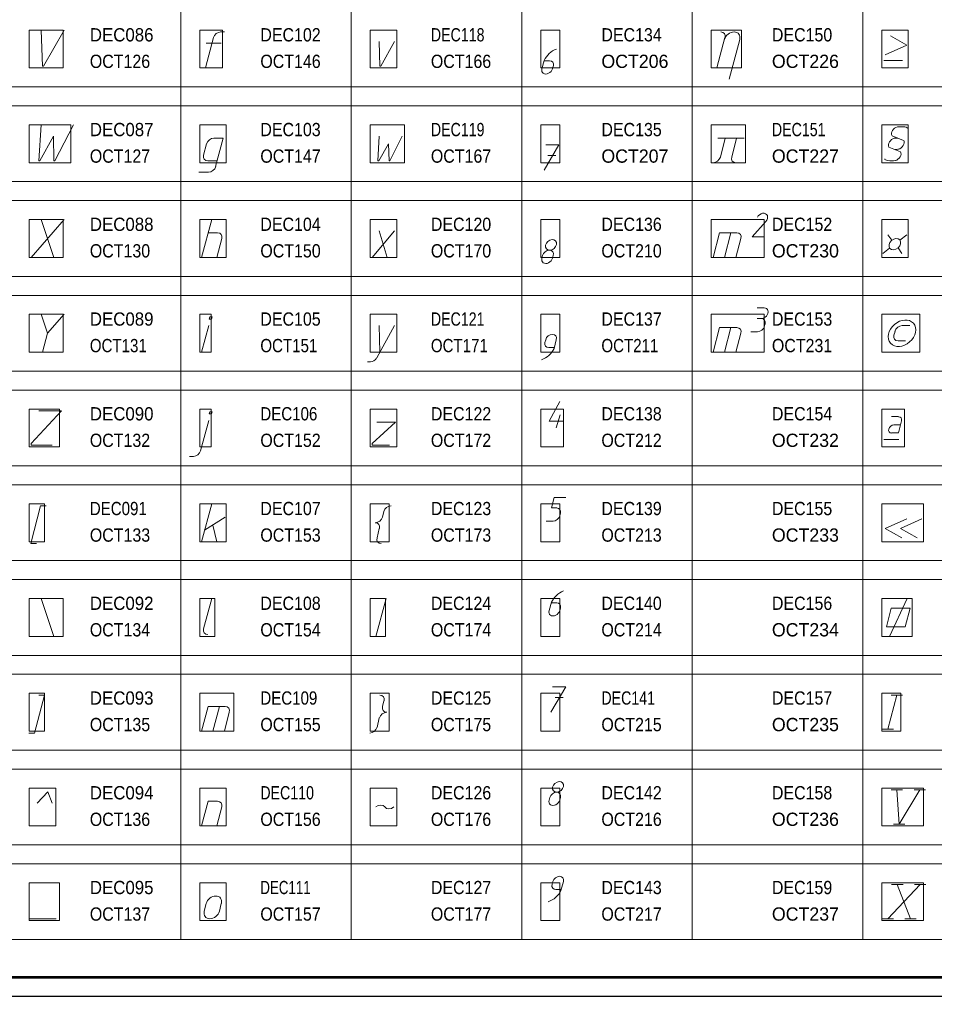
# Model space of a CAD drawing. Extents: x -200 to 7300, y -200 to 4800.
# Drawn here: x 2224 to 4639, y -200 to 2378 of the extents above; entities that cross this region are included whole.
import ezdxf

# ---------------------------------------------------------------- set-up
doc = ezdxf.new("R2010")
doc.units = 0
doc.header["$LTSCALE"] = 14
for name, color, linetype, lineweight in [('1', 7, 'Continuous', 13), ('5', 7, 'Continuous', 40), ('6', 7, 'Continuous', 13), ('63', 7, 'Continuous', 13)]:
    doc.layers.add(name, color=color, linetype=linetype, lineweight=lineweight)
doc.layers.add('10', color=7, linetype='Continuous')
doc.layers.add('11', color=7, linetype='Continuous')

msp = doc.modelspace()

# ---------------------------------------------------------------- linework, layer by layer
at = {"layer": '1'}
for p, q in [((2736, 2330), (2715, 2250)), ((2765, 2345), (2755, 2345)), ((4065, 2250), (4086, 2330)), ((4097, 2220), (4125, 2325)), ((2717, 2315), (2757, 2315)), ((3609, 2270), (3603, 2248)), ((3609, 2269), (3623, 2269)), ((4505, 2270), (4555, 2270)), ((3633, 2255), (3631, 2248)), ((4067, 2065), (4137, 2065)), ((4087, 2065), (4074, 2015)), ((4117, 2065), (4104, 2015)), ((4527, 2071), (4557.7, 2059)), ((2710.3, 2020), (2718.3, 2050)), ((4519, 2041), (4549.7, 2029)), ((3619, 2019), (3640, 2019)), ((2746, 2005), (2721, 2005)), ((2723, 1975), (2698, 1975)), ((2342, 1850), (2255, 1750)), ((2282, 1850), (2315, 1750)), ((2732, 1850), (2705, 1750)), ((2722.6, 1815), (2747, 1815)), ((3214, 1820), (3155, 1750)), ((3174, 1820), (3195, 1750)), ((4102, 1815), (4085, 1750)), ((4516, 1810), (4526.4, 1795.5)), ((4566, 1810), (4547.7, 1795.7)), ((2758.3, 1800), (2745, 1750)), ((4128, 1800), (4115, 1750)), ((3605, 1755), (3603.2, 1748.6)), ((3633, 1755), (3631, 1748)), ((4503, 1760), (4520.7, 1774.6)), ((4553, 1760), (4543, 1775)), ((4189, 1617), (4171, 1617)), ((4182, 1589), (4171, 1589)), ((4192, 1575), (4190, 1568)), ((2298, 1550), (2285, 1500)), ((2705, 1500), (2724, 1570)), ((3214, 1570), (3167, 1485)), ((3174, 1570), (3175, 1500)), ((4102, 1565), (4085, 1500)), ((4128, 1550), (4115, 1500)), ((4172, 1554), (4154, 1554)), ((4535, 1555), (4532, 1545)), ((4574, 1570), (4554, 1570)), ((3611, 1526), (3613, 1533)), ((3635, 1510), (3641, 1533)), ((4543, 1530), (4563, 1530)), ((3635.5, 1512), (3621, 1512)), ((3150, 1475), (3143, 1475)), ((2724, 1320), (2702.3, 1240)), ((3641, 1300), (3651, 1335)), ((4526, 1330), (4544, 1330)), ((4532, 1308), (4549.2, 1308)), ((4505, 1270), (4545, 1270)), ((2683, 1225), (2673, 1225)), ((2732, 1100), (2705, 1000)), ((2767, 1065), (2713, 1030)), ((3186, 1080), (3182, 1065)), ((3652, 1075), (3650, 1068)), ((2745, 1000), (2735, 1044)), ((3168, 1010), (3174, 1035)), ((3614, 1054), (3632, 1054)), ((2315, 750), (2282, 850)), ((2732, 850), (2710, 770)), ((3192, 850), (3165, 750)), ((3628, 840), (3622, 818)), ((3628, 839), (3642, 839)), ((3652, 825), (3650, 818)), ((4520, 750), (4567, 850)), ((4540, 595), (4516, 505)), ((4525, 595), (4555, 595)), ((3186, 580), (3182, 565)), ((3638, 589), (3659, 589)), ((2752, 565), (2735, 500)), ((2778, 550), (2765, 500)), ((3168, 510), (3174, 535)), ((4501, 505), (4531, 505)), ((4525, 345), (4555, 345)), ((4615, 345), (4585, 345)), ((3624, 325), (3622, 318)), ((3652, 325), (3650, 318)), ((2758, 300), (2745, 250)), ((4531, 255), (4561, 255)), ((3630, 96), (3632, 103)), ((3653.6, 82), (3640, 82)), ((3653, 80), (3660, 103)), ((4601, 95), (4516, 5)), ((4526, 95), (4556, 95)), ((4541, 95), (4576, 5)), ((4616, 95), (4586, 95)), ((2717, 45), (2712, 25)), ((2757, 45), (2752, 25)), ((2251, 5), (2321, 5)), ((4501, 5), (4531, 5)), ((4561, 5), (4591, 5))]:
    msp.add_line(p, q, dxfattribs=at)
for points in [[(2282, 2350), (2285, 2255), (2288, 2255), (2342, 2350)], [(3174, 2320), (3175, 2255), (3178, 2255), (3214, 2320)], [(4523, 2335), (4566, 2310), (4509, 2285)], [(2282, 2100), (2275, 2005), (2278, 2005), (2314, 2070), (2315, 2005), (2318, 2005), (2367, 2100)], [(2737, 2065), (2762, 2065), (2742, 1990)], [(3174, 2070), (3170, 2005), (3173, 2005), (3198, 2050), (3200, 2005), (3202, 2005), (3234, 2070)], [(3613, 2047), (3648, 2047), (3609, 1980)], [(4189, 1804), (4158, 1804), (4194, 1845)], [(4055, 1750), (4072, 1815), (4117, 1815)], [(2282, 1600), (2298, 1550), (2342, 1600)], [(4055, 1500), (4072, 1565), (4117, 1565)], [(3660, 1318), (3622, 1318), (3650, 1370)], [(2275, 1345), (2335, 1345), (2255, 1259), (2255, 1255), (2311, 1255)], [(3167, 1315), (3217, 1315), (3155, 1259), (3155, 1255), (3201, 1255)], [(4552, 1319), (4544, 1287), (4526, 1287)], [(3666, 1117), (3635, 1117), (3628, 1089), (3642, 1089)], [(2295, 1095), (2280, 1095), (2254, 995), (2269, 995)], [(4566, 1060), (4509, 1035), (4553, 1010)], [(4606, 1060), (4549, 1035), (4593, 1010)], [(2275, 595), (2290, 595), (2264, 495), (2249, 495)], [(3631, 617), (3666, 617), (3627, 550)], [(2705, 500), (2722, 565), (2767, 565)], [(2311, 310), (2299, 340), (2271, 310)], [(4540, 345), (4546, 255), (4600, 345)], [(2705, 250), (2722, 315), (2747, 315)]]:
    msp.add_lwpolyline(points, dxfattribs=at)
for points in [[(2725, 1587), (2731, 1587), (2733, 1593), (2727, 1593)], [(2725, 1337), (2731, 1337), (2733, 1343), (2727, 1343)], [(4512, 775), (4562, 775), (4575, 825), (4525, 825)]]:
    msp.add_lwpolyline(points, close=True, dxfattribs=at)
for centre, major_axis, ratio, start_param, end_param in [((2751.31, 2330), (-12.9, -11.29), 0.765566, 3.860429, 5.4312252), ((4071.33, 2330), (-12.9, -11.29), 0.765566, 2.2896327, 3.860429), ((4104.99, 2325), (-17.2, -15.05), 0.765566, 2.2896327, 5.4312253), ((3647.53, 2262.33), (-35.31, -30.9), 0.765566, 4.2695852, 5.2433836), ((3619.23, 2255), (-12.04, -10.54), 0.765566, 2.2896326, 3.8604289), ((3616.99, 2247.96), (-12.04, -10.54), 0.765566, 5.4286742, 8.5753689), ((4541.35, 2080), (-12.9, -11.29), 0.765566, 4.1387286, 6.0747263), ((4549.03, 2090), (-20.04, -0.36), 0.248806, 3.0702852, 5.1041698), ((2733.29, 2050), (-12.9, -11.29), 0.765566, 3.860429, 5.4312252), ((4533.32, 2050), (-12.9, -11.29), 0.765566, 4.1387286, 6.0747263), ((4541, 2060), (-20.04, -0.36), 0.248806, 4.6410815, 5.1041696), ((4543.32, 2050), (-12.9, -11.29), 0.765566, 0.9971359, 2.9331337), ((2725.25, 2020), (12.9, 11.29), 0.765566, 2.2896328, 3.860429), ((4058.93, 2015), (-12.9, -11.29), 0.765566, 0.7188363, 2.2896326), ((4118.93, 2015), (12.9, 11.29), 0.765566, 2.2896328, 3.860429), ((4535.64, 2040), (-20.04, -0.36), 0.248806, 1.4994889, 2.0118784), ((4535.28, 2020), (-12.9, -11.29), 0.765566, 0.9971359, 2.9331337), ((2727.22, 1990), (-12.9, -11.29), 0.765566, 0.7188363, 2.2896326), ((4527.6, 2010), (-20.04, -0.36), 0.248806, 6.2118779, 8.2950638), ((4184.28, 1852.61), (-12.04, -10.54), 0.765566, 1.7153279, 5.1862467), ((2743.31, 1800), (-12.9, -11.29), 0.765566, 2.2896327, 3.860429), ((4113.33, 1800), (-12.9, -11.29), 0.765566, 2.2896327, 3.860429), ((3619, 1755), (-12.04, -10.54), 0.765566, 2.2896326, 5.4312252), ((3617.01, 1748.04), (-12.04, -10.54), 0.765566, 5.3918972, 8.5753689), ((4185.55, 1602.98), (-12.06, -10.55), 0.765566, 0.646299, 3.8615683), ((4178.04, 1575), (-12.04, -10.54), 0.765566, 2.2896326, 3.8604289), ((3627, 1533), (-12.04, -10.54), 0.765566, 2.2896326, 5.4312252), ((4113.34, 1550), (-12.9, -11.29), 0.765566, 2.2896327, 3.860429), ((4176.17, 1568), (12.04, 10.54), 0.765566, 3.860429, 5.4312252), ((4549.69, 1555), (-12.9, -11.29), 0.765566, 3.860429, 5.4312252), ((3625, 1526), (12.04, 10.54), 0.765566, 2.2896328, 3.860429), ((4547.01, 1545), (12.9, 11.29), 0.765566, 2.2896328, 3.860429), ((3598.42, 1516.52), (33.44, 29.26), 0.765566, 4.2103523, 5.2626218), ((3154.32, 1490), (12.9, 11.29), 0.765566, 3.8604291, 5.0573215), ((4541.45, 1319), (-9.22, -8.06), 0.765566, 2.2896327, 3.860429), ((4529.13, 1297.29), (-9.22, -8.06), 0.765566, 3.860429, 7.0020216), ((2687.26, 1240), (-12.9, -11.29), 0.765566, 0.7188363, 2.2896326), ((3201, 1080), (-12.9, -11.29), 0.765566, 3.860429, 5.4312252), ((3638.07, 1075), (-12.04, -10.54), 0.765566, 2.2896326, 3.8604289), ((3167.38, 1065), (-12.9, -11.29), 0.765566, 0.7188363, 2.2896326), ((3636.19, 1068), (12.04, 10.54), 0.765566, 3.860429, 5.4312252), ((3159.34, 1035), (-12.9, -11.29), 0.765566, 2.2896327, 3.860429), ((3183, 1010), (12.9, 11.29), 0.765566, 2.2896328, 3.860429), ((3666.38, 832.33), (-35.31, -30.9), 0.765566, 4.2695852, 5.2433836), ((3638.08, 825), (-12.04, -10.54), 0.765566, 2.2896326, 3.8604289), ((3636.01, 818.04), (-12.04, -10.54), 0.765566, 5.4286742, 8.5753689), ((2725.33, 770), (12.9, 11.29), 0.765566, 2.2896327, 3.860429), ((3171.43, 580), (-12.9, -11.29), 0.765566, 2.2896328, 3.8604291), ((2763, 550), (-12.9, -11.29), 0.765566, 2.2896327, 3.860429), ((3189.37, 535), (-12.9, -11.29), 0.765566, 3.8604291, 5.4312254), ((3197.41, 565), (12.9, 11.29), 0.765566, 2.2896328, 3.860429), ((3152.68, 510), (-12.9, -11.29), 0.765566, 0.7188363, 2.2896326), ((3638.11, 325), (-12.04, -10.54), 0.765566, 2.2896326, 5.4312252), ((2743, 300), (-12.9, -11.29), 0.765566, 2.2896327, 3.860429), ((3636.01, 318.04), (-12.04, -10.54), 0.765566, 5.4286742, 8.5753689), ((3173.19, 288), (-14.6, -12.77), 0.765566, 3.0750308, 4.6457939), ((3203.63, 312), (-14.6, -12.77), 0.765566, 6.2166235, 7.7873867), ((3646, 103), (-12.04, -10.54), 0.765566, 2.2896326, 5.4312252), ((3616.42, 86.52), (33.44, 29.26), 0.765566, 4.2103523, 5.2626218), ((3644, 96), (12.04, 10.54), 0.765566, 2.2896328, 3.860429), ((2737.08, 45), (-17.2, -15.05), 0.765566, 2.2896326, 5.4312252), ((2732, 25), (17.2, 15.05), 0.765566, 2.2896328, 5.4312254)]:
    msp.add_ellipse(centre, major_axis=major_axis, ratio=ratio, start_param=start_param, end_param=end_param, dxfattribs=at)
for centre, major_axis in [((3626.94, 1782.99), (-12.04, -10.54)), ((4534.31, 1785), (-12.9, -11.29)), ((4553.35, 1550), (-30.11, -26.34)), ((3645.64, 353), (-12.04, -10.54))]:
    msp.add_ellipse(centre, major_axis=major_axis, ratio=0.765566, dxfattribs=at)
at = {"layer": '5', "lineweight": 53}
msp.add_line((7150, -150), (-50, -150), dxfattribs=at)
at = {"layer": '5', "lineweight": 25}
msp.add_lwpolyline([(-200, -200), (-200, 4800), (7300, 4800), (7300, -200)], close=True, dxfattribs=at)
at = {"layer": '6'}
for p, q in [((2650, 3950), (2650, -50)), ((3100, 3950), (3100, -50)), ((3550, 3950), (3550, -50)), ((4000, 3950), (4000, -50)), ((4450, 3950), (4450, -50)), ((-50, 2200), (7150, 2200)), ((-50, 2150), (7150, 2150)), ((-50, 1950), (7150, 1950)), ((-50, 1900), (7150, 1900)), ((-50, 1700), (7150, 1700)), ((-50, 1650), (7150, 1650)), ((-50, 1450), (7150, 1450)), ((-50, 1400), (7150, 1400)), ((-50, 1200), (7150, 1200)), ((-50, 1150), (7150, 1150)), ((-50, 950), (7150, 950)), ((-50, 900), (7150, 900)), ((-50, 700), (7150, 700)), ((-50, 650), (7150, 650)), ((-50, 450), (7150, 450)), ((-50, 400), (7150, 400)), ((-50, 200), (7150, 200)), ((-50, 150), (7150, 150)), ((-50, -50), (7150, -50))]:
    msp.add_line(p, q, dxfattribs=at)
at = {"layer": '63'}
for points in [[(2250, 2250), (2340, 2250), (2340, 2350), (2250, 2350)], [(2700, 2250), (2760, 2250), (2760, 2350), (2700, 2350)], [(3150, 2250), (3220, 2250), (3220, 2350), (3150, 2350)], [(3600, 2250), (3650, 2250), (3650, 2350), (3600, 2350)], [(4050, 2250), (4130, 2250), (4130, 2350), (4050, 2350)], [(4500, 2250), (4570, 2250), (4570, 2350), (4500, 2350)], [(2250, 2000), (2360, 2000), (2360, 2100), (2250, 2100)], [(2700, 2000), (2770, 2000), (2770, 2100), (2700, 2100)], [(3150, 2000), (3240, 2000), (3240, 2100), (3150, 2100)], [(3600, 2000), (3650, 2000), (3650, 2100), (3600, 2100)], [(4050, 2000), (4140, 2000), (4140, 2100), (4050, 2100)], [(4500, 2000), (4570, 2000), (4570, 2100), (4500, 2100)], [(2250, 1750), (2340, 1750), (2340, 1850), (2250, 1850)], [(2700, 1750), (2770, 1750), (2770, 1850), (2700, 1850)], [(3150, 1750), (3220, 1750), (3220, 1850), (3150, 1850)], [(3600, 1750), (3650, 1750), (3650, 1850), (3600, 1850)], [(4050, 1750), (4190, 1750), (4190, 1850), (4050, 1850)], [(4500, 1750), (4570, 1750), (4570, 1850), (4500, 1850)], [(2250, 1500), (2340, 1500), (2340, 1600), (2250, 1600)], [(2700, 1500), (2730, 1500), (2730, 1600), (2700, 1600)], [(3150, 1500), (3220, 1500), (3220, 1600), (3150, 1600)], [(3600, 1500), (3650, 1500), (3650, 1600), (3600, 1600)], [(4050, 1500), (4190, 1500), (4190, 1600), (4050, 1600)], [(4500, 1500), (4600, 1500), (4600, 1600), (4500, 1600)], [(2250, 1250), (2330, 1250), (2330, 1350), (2250, 1350)], [(2700, 1250), (2730, 1250), (2730, 1350), (2700, 1350)], [(3150, 1250), (3220, 1250), (3220, 1350), (3150, 1350)], [(3600, 1250), (3660, 1250), (3660, 1350), (3600, 1350)], [(4500, 1250), (4560, 1250), (4560, 1350), (4500, 1350)], [(2250, 1000), (2290, 1000), (2290, 1100), (2250, 1100)], [(2700, 1000), (2770, 1000), (2770, 1100), (2700, 1100)], [(3150, 1000), (3200, 1000), (3200, 1100), (3150, 1100)], [(3600, 1000), (3650, 1000), (3650, 1100), (3600, 1100)], [(4500, 1000), (4610, 1000), (4610, 1100), (4500, 1100)], [(2250, 750), (2340, 750), (2340, 850), (2250, 850)], [(2700, 750), (2740, 750), (2740, 850), (2700, 850)], [(3150, 750), (3190, 750), (3190, 850), (3150, 850)], [(3600, 750), (3650, 750), (3650, 850), (3600, 850)], [(4500, 750), (4580, 750), (4580, 850), (4500, 850)], [(2250, 500), (2290, 500), (2290, 600), (2250, 600)], [(2700, 500), (2790, 500), (2790, 600), (2700, 600)], [(3150, 500), (3200, 500), (3200, 600), (3150, 600)], [(3600, 500), (3650, 500), (3650, 600), (3600, 600)], [(4500, 500), (4550, 500), (4550, 600), (4500, 600)], [(2250, 250), (2320, 250), (2320, 350), (2250, 350)], [(2700, 250), (2770, 250), (2770, 350), (2700, 350)], [(3150, 250), (3220, 250), (3220, 350), (3150, 350)], [(3600, 250), (3650, 250), (3650, 350), (3600, 350)], [(4500, 250), (4610, 250), (4610, 350), (4500, 350)], [(2250, 0), (2330, 0), (2330, 100), (2250, 100)], [(2700, 0), (2770, 0), (2770, 100), (2700, 100)], [(3600, 0), (3650, 0), (3650, 100), (3600, 100)], [(4500, 0), (4610, 0), (4610, 100), (4500, 100)]]:
    msp.add_lwpolyline(points, close=True, dxfattribs=at)

# ---------------------------------------------------------------- texts
at = {"layer": '10'}
for s, width, p in [('DEC086', 0.95, (2410, 2320)), ('DEC102', 0.9, (2860, 2320)), ('DEC118', 0.8, (3310, 2320)), ('DEC134', 0.9, (3760, 2320)), ('DEC150', 0.9, (4210, 2320)), ('DEC087', 0.95, (2410, 2070)), ('DEC103', 0.9, (2860, 2070)), ('DEC119', 0.8, (3310, 2070)), ('DEC135', 0.9, (3760, 2070)), ('DEC151', 0.8, (4210, 2070)), ('DEC088', 0.95, (2410, 1820)), ('DEC104', 0.9, (2860, 1820)), ('DEC120', 0.9, (3310, 1820)), ('DEC136', 0.9, (3760, 1820)), ('DEC152', 0.9, (4210, 1820)), ('DEC089', 0.95, (2410, 1570)), ('DEC105', 0.9, (2860, 1570)), ('DEC121', 0.8, (3310, 1570)), ('DEC137', 0.9, (3760, 1570)), ('DEC153', 0.9, (4210, 1570)), ('DEC090', 0.95, (2410, 1320)), ('DEC106', 0.85, (2860, 1320)), ('DEC122', 0.9, (3310, 1320)), ('DEC138', 0.9, (3760, 1320)), ('DEC154', 0.9, (4210, 1320)), ('DEC091', 0.85, (2410, 1070)), ('DEC107', 0.9, (2860, 1070)), ('DEC123', 0.9, (3310, 1070)), ('DEC139', 0.9, (3760, 1070)), ('DEC155', 0.9, (4210, 1070)), ('DEC092', 0.95, (2410, 820)), ('DEC108', 0.9, (2860, 820)), ('DEC124', 0.9, (3310, 820)), ('DEC140', 0.9, (3760, 820)), ('DEC156', 0.9, (4210, 820)), ('DEC093', 0.95, (2410, 570)), ('DEC109', 0.85, (2860, 570)), ('DEC125', 0.9, (3310, 570)), ('DEC141', 0.8, (3760, 570)), ('DEC157', 0.9, (4210, 570)), ('DEC094', 0.95, (2410, 320)), ('DEC110', 0.8, (2860, 320)), ('DEC126', 0.9, (3310, 320)), ('DEC142', 0.9, (3760, 320)), ('DEC158', 0.9, (4210, 320)), ('DEC095', 0.95, (2410, 70)), ('DEC111', 0.75, (2860, 70)), ('DEC127', 0.9, (3310, 70)), ('DEC143', 0.9, (3760, 70)), ('DEC159', 0.9, (4210, 70))]:
    msp.add_text(s, height=35, dxfattribs=dict(at, width=width)).set_placement(p)
at = {"layer": '11'}
for s, width, p in [('OCT126', 0.9, (2410, 2250)), ('OCT146', 0.9, (2860, 2250)), ('OCT166', 0.9, (3310, 2250)), ('OCT127', 0.9, (2410, 2000)), ('OCT147', 0.9, (2860, 2000)), ('OCT167', 0.9, (3310, 2000)), ('OCT130', 0.9, (2410, 1750)), ('OCT150', 0.9, (2860, 1750)), ('OCT170', 0.9, (3310, 1750)), ('OCT210', 0.9, (3760, 1750)), ('OCT131', 0.85, (2410, 1500)), ('OCT151', 0.85, (2860, 1500)), ('OCT171', 0.85, (3310, 1500)), ('OCT211', 0.85, (3760, 1500)), ('OCT231', 0.9, (4210, 1500)), ('OCT132', 0.9, (2410, 1250)), ('OCT152', 0.9, (2860, 1250)), ('OCT172', 0.9, (3310, 1250)), ('OCT212', 0.9, (3760, 1250)), ('OCT133', 0.9, (2410, 1000)), ('OCT153', 0.9, (2860, 1000)), ('OCT173', 0.9, (3310, 1000)), ('OCT213', 0.9, (3760, 1000)), ('OCT134', 0.9, (2410, 750)), ('OCT154', 0.9, (2860, 750)), ('OCT174', 0.9, (3310, 750)), ('OCT214', 0.9, (3760, 750)), ('OCT135', 0.9, (2410, 500)), ('OCT155', 0.9, (2860, 500)), ('OCT175', 0.9, (3310, 500)), ('OCT215', 0.9, (3760, 500)), ('OCT136', 0.9, (2410, 250)), ('OCT156', 0.9, (2860, 250)), ('OCT176', 0.9, (3310, 250)), ('OCT216', 0.9, (3760, 250)), ('OCT137', 0.9, (2410, 0)), ('OCT157', 0.9, (2860, 0)), ('OCT177', 0.9, (3310, 0)), ('OCT217', 0.9, (3760, 0))]:
    msp.add_text(s, height=35, dxfattribs=dict(at, width=width)).set_placement(p)
for s, p in [('OCT206', (3760, 2250)), ('OCT226', (4210, 2250)), ('OCT207', (3760, 2000)), ('OCT227', (4210, 2000)), ('OCT230', (4210, 1750)), ('OCT232', (4210, 1250)), ('OCT233', (4210, 1000)), ('OCT234', (4210, 750)), ('OCT235', (4210, 500)), ('OCT236', (4210, 250)), ('OCT237', (4210, 0))]:
    msp.add_text(s, height=35, dxfattribs=at).set_placement(p)

doc.saveas('drawing.dxf')
